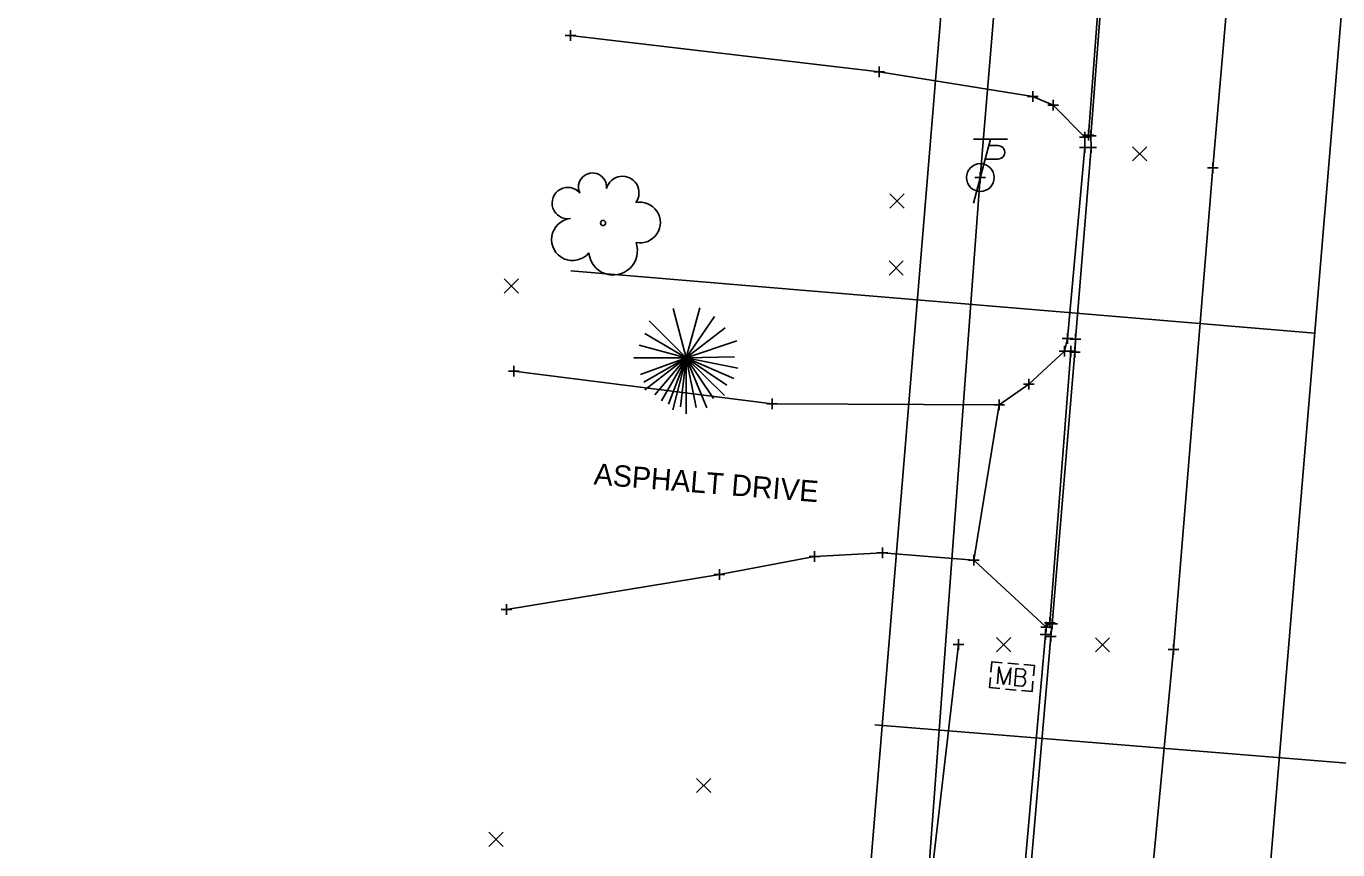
# Model space of a CAD drawing. Extents: x 1380440 to 1381945, y 468756 to 470369.
# Drawn here: x 1381439.7 to 1381562.7, y 469327.1 to 469404.3 of the extents above; entities that cross this region are included whole.
import ezdxf

# ---------------------------------------------------------------- set-up
doc = ezdxf.new("R2010")
doc.units = 0
for name, color, linetype in [('DR_X_Cells', 7, 'Continuous'), ('GE_P_Driveway_CL', 7, 'Continuous'), ('PM_X_CL_Double_Solid', 7, 'Continuous'), ('PV_P_Curb', 7, 'Continuous'), ('PV_X_COP', 7, 'Continuous'), ('RD_P_Cells', 7, 'Continuous'), ('RW_P_Esmt_TMP', 7, 'Continuous'), ('RW_X_Esmt_SH', 7, 'Continuous'), ('SC_Scratch10', 7, 'Continuous'), ('SC_Shading1', 7, 'Continuous'), ('SH_Named_Boundary', 7, 'Continuous'), ('UT_X_Gas', 7, 'Continuous'), ('UT_X_Overhead_Combined', 7, 'Continuous'), ('UT_X_Sanitary_Line', 7, 'Continuous'), ('UT_X_Water', 7, 'Continuous'), ('X-SUBDIVISION', 7, 'Continuous')]:
    doc.layers.add(name, color=color, linetype=linetype)

msp = doc.modelspace()

# ---------------------------------------------------------------- linework, layer by layer
at = {"layer": 'DR_X_Cells'}
for points in [[(1381538.96, 469393.9), (1381538.97, 469392.95), (1381537.34, 469375.04), (1381537.07, 469373.85)], [(1381535.34, 469347.99), (1381535.28, 469347.29), (1381533.36, 469325.49), (1381531.78, 469307.95), (1381530.98, 469305.57), (1381527.65, 469300.02), (1381527.35, 469296.02), (1381529.77, 469292.16), (1381529.97, 469291.26), (1381530.24, 469290.52)]]:
    msp.add_lwpolyline(points, dxfattribs=at)
at = {"layer": 'GE_P_Driveway_CL'}
for p, q in [((1381543.45, 469391.67), (1381544.78, 469393.01)), ((1381543.45, 469393.01), (1381544.78, 469391.67)), ((1381520.69, 469387.24), (1381522.03, 469388.58)), ((1381520.69, 469388.58), (1381522.03, 469387.24)), ((1381520.62, 469380.98), (1381521.95, 469382.32)), ((1381520.62, 469382.32), (1381521.95, 469380.98)), ((1381484.53, 469379.29), (1381485.86, 469380.63)), ((1381484.53, 469380.63), (1381485.86, 469379.29)), ((1381530.69, 469345.66), (1381532.03, 469347)), ((1381530.69, 469347), (1381532.03, 469345.66)), ((1381539.96, 469345.66), (1381541.3, 469346.99)), ((1381539.96, 469346.99), (1381541.3, 469345.66)), ((1381502.57, 469332.47), (1381503.9, 469333.8)), ((1381502.57, 469333.8), (1381503.9, 469332.47)), ((1381483.09, 469327.43), (1381484.43, 469328.77)), ((1381483.09, 469328.77), (1381484.43, 469327.43))]:
    msp.add_line(p, q, dxfattribs=at)
at = {"layer": 'PM_X_CL_Double_Solid'}
msp.add_lwpolyline([(1381555.39, 469442.03), (1381550.97, 469391.02), (1381547.28, 469345.9), (1381541.95, 469289.55), (1381537.19, 469231.27), (1381533.05, 469168.09), (1381530.32, 469133.74), (1381523.97, 469065.08), (1381520.12, 469021.37), (1381518.18, 469001.31)], dxfattribs=at)
at = {"layer": 'PV_P_Curb'}
msp.add_lwpolyline([(1381527.14, 469346.36), (1381524.79, 469326.2), (1381523.85, 469304.1), (1381523.31, 469298.29)], dxfattribs=at)
at = {"layer": 'PV_X_COP'}
for p, q in [((1381530.13, 469393.72), (1381528.52, 469387.72)), ((1381531.73, 469393.72), (1381528.53, 469393.72)), ((1381529.97, 469393.12), (1381530.82, 469393.12)), ((1381529.63, 469391.85), (1381530.82, 469391.85))]:
    msp.add_line(p, q, dxfattribs=at)
msp.add_circle((1381529.17, 469390.12), 1.3, dxfattribs=at)
msp.add_arc((1381530.83, 469392.48), 0.638, 268.8767, 91.1233, dxfattribs=at)
at = {"layer": 'RD_P_Cells'}
for p, q in [((1381531.74, 469344.6), (1381532.74, 469344.51)), ((1381532.14, 469343.34), (1381532.14, 469343.34)), ((1381531.52, 469342.17), (1381532.52, 469342.08))]:
    msp.add_line(p, q, dxfattribs=at)
for points in [[(1381530.17, 469343.77), (1381530.26, 469344.74), (1381531.23, 469344.65)], [(1381530.78, 469342.66), (1381530.92, 469344.25), (1381531.36, 469342.61), (1381532.05, 469344.15), (1381531.91, 469342.56)], [(1381533.17, 469343.32), (1381533.23, 469343.37), (1381533.28, 469343.41), (1381533.3, 469343.44), (1381533.32, 469343.47), (1381533.35, 469343.51), (1381533.36, 469343.55), (1381533.4, 469343.64), (1381533.4, 469343.67), (1381533.41, 469343.72), (1381533.4, 469343.8), (1381533.38, 469343.87), (1381533.35, 469343.92), (1381533.29, 469343.98), (1381533.24, 469344), (1381533.22, 469344.02), (1381533.16, 469344.05), (1381532.54, 469344.11), (1381532.4, 469342.51), (1381533.09, 469342.45), (1381533.18, 469342.49), (1381533.26, 469342.55), (1381533.33, 469342.64), (1381533.38, 469342.75), (1381533.4, 469342.86), (1381533.41, 469342.94), (1381533.39, 469343.02), (1381533.35, 469343.13), (1381533.3, 469343.22), (1381533.17, 469343.32), (1381532.48, 469343.38)], [(1381533.26, 469344.47), (1381534.24, 469344.37), (1381534.16, 469343.41)], [(1381531.01, 469342.22), (1381530.04, 469342.31), (1381530.13, 469343.27)], [(1381534.11, 469342.91), (1381534.02, 469341.94), (1381533.03, 469342.03)]]:
    msp.add_lwpolyline(points, dxfattribs=at)
at = {"layer": 'RW_P_Esmt_TMP'}
msp.add_line((1381533.72, 469370.74), (1381533.72, 469370.74), dxfattribs=at)
msp.add_lwpolyline([(1381541, 469413.22), (1381539.53, 469394.02), (1381539.58, 469392.93), (1381538.09, 469374.98), (1381538.03, 469373.76), (1381535.92, 469348.28), (1381535.79, 469347.09), (1381533.91, 469325.42), (1381532.32, 469307.8), (1381531.56, 469305.55), (1381528.19, 469299.9), (1381527.99, 469296.13), (1381530.34, 469292.53), (1381530.8, 469290.75), (1381530.92, 469290), (1381529.4, 469268.09), (1381529.3, 469267.44), (1381526.47, 469232.31)], dxfattribs=at)
at = {"layer": 'RW_X_Esmt_SH'}
for points in [[(1381540.26, 469413.42), (1381540.77, 469413.29), (1381539.31, 469394.1), (1381538.96, 469393.9)], [(1381490.75, 469403.42), (1381519.7, 469400.04), (1381534.11, 469397.71), (1381535.99, 469396.91), (1381538.96, 469393.9)], [(1381537.07, 469373.85), (1381533.72, 469370.74), (1381530.94, 469368.81), (1381528.58, 469354.27), (1381535.34, 469347.99)], [(1381537.07, 469373.85), (1381537.66, 469373.84), (1381535.7, 469348.38), (1381535.34, 469347.99)], [(1381530.94, 469368.81), (1381509.64, 469368.9), (1381485.43, 469371.98)], [(1381484.73, 469349.64), (1381504.73, 469352.92), (1381513.61, 469354.59), (1381519.99, 469354.96), (1381528.58, 469354.27)]]:
    msp.add_lwpolyline(points, dxfattribs=at)
at = {"layer": 'SC_Scratch10'}
for p, q in [((1381501.6, 469373.21), (1381500.37, 469377.83)), ((1381501.6, 469373.21), (1381502.86, 469377.91)), ((1381501.6, 469373.21), (1381498.11, 469376.7)), ((1381501.6, 469373.21), (1381504.26, 469377.1)), ((1381501.6, 469373.21), (1381505.26, 469376.02)), ((1381501.6, 469373.21), (1381497.7, 469375.51)), ((1381501.6, 469373.21), (1381506.34, 469374.82)), ((1381501.6, 469373.21), (1381497.19, 469374.4)), ((1381496.67, 469373.21), (1381501.6, 469373.21)), ((1381501.6, 469373.21), (1381497.31, 469371.65)), ((1381501.6, 469373.21), (1381497.62, 469370.93)), ((1381501.6, 469373.21), (1381497.7, 469370.22)), ((1381501.6, 469373.21), (1381498.66, 469369.75)), ((1381501.6, 469373.21), (1381499.28, 469369.2)), ((1381501.6, 469373.21), (1381499.94, 469368.87)), ((1381501.6, 469373.21), (1381500.34, 469368.36)), ((1381501.6, 469373.21), (1381501.06, 469368.62)), ((1381501.6, 469373.21), (1381506.11, 469373.3)), ((1381501.6, 469367.97), (1381501.6, 469373.21)), ((1381501.6, 469373.21), (1381502.52, 469368.58)), ((1381501.6, 469373.21), (1381503.54, 469368.54)), ((1381501.6, 469373.21), (1381504.14, 469369.42)), ((1381501.6, 469373.21), (1381505.19, 469369.69)), ((1381501.6, 469373.21), (1381505.42, 469370.66)), ((1381501.6, 469373.21), (1381506.07, 469371.27)), ((1381501.6, 469373.21), (1381506.43, 469372.25))]:
    msp.add_line(p, q, dxfattribs=at)
msp.add_circle((1381493.8, 469385.86), 0.24, dxfattribs=at)
for centre, radius, start, end in [((1381492.81, 469389.23), 1.32, 354.0047, 205.9741), ((1381495.62, 469388.69), 1.55, 323.83, 165.0376), ((1381490.49, 469387.73), 1.47, 39.0625, 279.5412), ((1381497.26, 469385.9), 1.91, 259.1453, 101.4596), ((1381490.94, 469384.31), 1.97, 96.1722, 320.5737), ((1381494.74, 469383.26), 2.28, 184.9476, 19.4572)]:
    msp.add_arc(centre, radius, start, end, dxfattribs=at)
at = {"layer": 'SC_Shading1'}
msp.add_lwpolyline([(1381555.39, 469442.03), (1381550.97, 469391.02), (1381547.28, 469345.9), (1381541.95, 469289.55), (1381537.19, 469231.27), (1381533.05, 469168.09), (1381530.32, 469133.74), (1381523.97, 469065.08), (1381520.12, 469021.37), (1381518.18, 469001.31)], dxfattribs=at)
at = {"layer": 'SH_Named_Boundary'}
for p, q in [((1381490.25, 469403.42), (1381491.25, 469403.42)), ((1381490.75, 469403.92), (1381490.75, 469402.92)), ((1381490.75, 469403.42), (1381490.75, 469403.42)), ((1381519.7, 469400.54), (1381519.7, 469399.54)), ((1381519.2, 469400.04), (1381520.2, 469400.04)), ((1381519.7, 469400.04), (1381519.7, 469400.04)), ((1381534.11, 469398.21), (1381534.11, 469397.21)), ((1381533.61, 469397.71), (1381534.61, 469397.71)), ((1381534.11, 469397.71), (1381534.11, 469397.71)), ((1381535.49, 469396.91), (1381536.49, 469396.91)), ((1381535.99, 469397.41), (1381535.99, 469396.41)), ((1381535.99, 469396.91), (1381535.99, 469396.91)), ((1381538.96, 469394.4), (1381538.96, 469393.4)), ((1381538.96, 469394.4), (1381538.96, 469393.4)), ((1381538.96, 469394.4), (1381538.96, 469393.4)), ((1381539.31, 469394.6), (1381539.31, 469393.6)), ((1381539.53, 469394.52), (1381539.53, 469393.52)), ((1381538.46, 469393.9), (1381539.46, 469393.9)), ((1381538.46, 469393.9), (1381539.46, 469393.9)), ((1381538.46, 469393.9), (1381539.46, 469393.9)), ((1381538.81, 469394.1), (1381539.81, 469394.1)), ((1381538.96, 469393.9), (1381538.96, 469393.9)), ((1381538.96, 469393.9), (1381538.96, 469393.9)), ((1381538.96, 469393.9), (1381538.96, 469393.9)), ((1381538.97, 469393.45), (1381538.97, 469392.45)), ((1381539.03, 469394.02), (1381540.03, 469394.02)), ((1381539.31, 469394.1), (1381539.31, 469394.1)), ((1381539.53, 469394.02), (1381539.53, 469394.02)), ((1381539.58, 469393.43), (1381539.58, 469392.43)), ((1381538.47, 469392.95), (1381539.47, 469392.95)), ((1381538.97, 469392.95), (1381538.97, 469392.95)), ((1381539.08, 469392.93), (1381540.08, 469392.93)), ((1381539.58, 469392.93), (1381539.58, 469392.93)), ((1381550.47, 469391.02), (1381551.47, 469391.02)), ((1381550.97, 469391.52), (1381550.97, 469390.52)), ((1381550.97, 469391.02), (1381550.97, 469391.02)), ((1381528.67, 469390.12), (1381529.67, 469390.12)), ((1381528.67, 469390.12), (1381529.67, 469390.12)), ((1381529.17, 469390.62), (1381529.17, 469389.62)), ((1381529.17, 469390.62), (1381529.17, 469389.62)), ((1381529.17, 469390.12), (1381529.17, 469390.12)), ((1381529.17, 469390.12), (1381529.17, 469390.12)), ((1381536.84, 469375.04), (1381537.84, 469375.04)), ((1381537.34, 469375.54), (1381537.34, 469374.54)), ((1381537.34, 469375.04), (1381537.34, 469375.04)), ((1381537.59, 469374.98), (1381538.59, 469374.98)), ((1381538.09, 469375.48), (1381538.09, 469374.48)), ((1381538.09, 469374.98), (1381538.09, 469374.98)), ((1381536.57, 469373.85), (1381537.57, 469373.85)), ((1381536.57, 469373.85), (1381537.57, 469373.85)), ((1381536.57, 469373.85), (1381537.57, 469373.85)), ((1381537.07, 469374.35), (1381537.07, 469373.35)), ((1381537.07, 469374.35), (1381537.07, 469373.35)), ((1381537.07, 469374.35), (1381537.07, 469373.35)), ((1381537.07, 469373.85), (1381537.07, 469373.85)), ((1381537.07, 469373.85), (1381537.07, 469373.85)), ((1381537.07, 469373.85), (1381537.07, 469373.85)), ((1381537.16, 469373.84), (1381538.16, 469373.84)), ((1381537.53, 469373.76), (1381538.53, 469373.76)), ((1381537.66, 469374.34), (1381537.66, 469373.34)), ((1381537.66, 469373.84), (1381537.66, 469373.84)), ((1381538.03, 469374.26), (1381538.03, 469373.26)), ((1381538.03, 469373.76), (1381538.03, 469373.76)), ((1381485.43, 469372.48), (1381485.43, 469371.48)), ((1381484.93, 469371.98), (1381485.93, 469371.98)), ((1381485.43, 469371.98), (1381485.43, 469371.98)), ((1381533.72, 469371.24), (1381533.72, 469370.24)), ((1381533.72, 469371.24), (1381533.72, 469370.24)), ((1381533.22, 469370.74), (1381534.22, 469370.74)), ((1381533.22, 469370.74), (1381534.22, 469370.74)), ((1381533.72, 469370.74), (1381533.72, 469370.74)), ((1381533.72, 469370.74), (1381533.72, 469370.74)), ((1381509.14, 469368.9), (1381510.14, 469368.9)), ((1381509.64, 469369.4), (1381509.64, 469368.4)), ((1381509.64, 469368.9), (1381509.64, 469368.9)), ((1381530.44, 469368.81), (1381531.44, 469368.81)), ((1381530.44, 469368.81), (1381531.44, 469368.81)), ((1381530.94, 469369.31), (1381530.94, 469368.31)), ((1381530.94, 469369.31), (1381530.94, 469368.31)), ((1381530.94, 469368.81), (1381530.94, 469368.81)), ((1381530.94, 469368.81), (1381530.94, 469368.81)), ((1381513.61, 469355.09), (1381513.61, 469354.09)), ((1381519.99, 469355.46), (1381519.99, 469354.46)), ((1381513.11, 469354.59), (1381514.11, 469354.59)), ((1381513.61, 469354.59), (1381513.61, 469354.59)), ((1381519.49, 469354.96), (1381520.49, 469354.96)), ((1381519.99, 469354.96), (1381519.99, 469354.96)), ((1381528.08, 469354.27), (1381529.08, 469354.27)), ((1381528.08, 469354.27), (1381529.08, 469354.27)), ((1381528.58, 469354.77), (1381528.58, 469353.77)), ((1381528.58, 469354.77), (1381528.58, 469353.77)), ((1381528.58, 469354.27), (1381528.58, 469354.27)), ((1381528.58, 469354.27), (1381528.58, 469354.27)), ((1381504.23, 469352.92), (1381505.23, 469352.92)), ((1381504.73, 469353.42), (1381504.73, 469352.42)), ((1381504.73, 469352.92), (1381504.73, 469352.92)), ((1381484.73, 469350.14), (1381484.73, 469349.14)), ((1381484.23, 469349.64), (1381485.23, 469349.64)), ((1381484.73, 469349.64), (1381484.73, 469349.64)), ((1381535.7, 469348.88), (1381535.7, 469347.88)), ((1381534.84, 469347.99), (1381535.84, 469347.99)), ((1381534.84, 469347.99), (1381535.84, 469347.99)), ((1381534.84, 469347.99), (1381535.84, 469347.99)), ((1381535.2, 469348.38), (1381536.2, 469348.38)), ((1381535.28, 469347.79), (1381535.28, 469346.79)), ((1381535.34, 469348.49), (1381535.34, 469347.49)), ((1381535.34, 469348.49), (1381535.34, 469347.49)), ((1381535.34, 469348.49), (1381535.34, 469347.49)), ((1381535.34, 469347.99), (1381535.34, 469347.99)), ((1381535.34, 469347.99), (1381535.34, 469347.99)), ((1381535.34, 469347.99), (1381535.34, 469347.99)), ((1381535.42, 469348.28), (1381536.42, 469348.28)), ((1381535.7, 469348.38), (1381535.7, 469348.38)), ((1381535.92, 469348.78), (1381535.92, 469347.78)), ((1381535.92, 469348.28), (1381535.92, 469348.28)), ((1381527.14, 469346.86), (1381527.14, 469345.86)), ((1381534.78, 469347.29), (1381535.78, 469347.29)), ((1381535.28, 469347.29), (1381535.28, 469347.29)), ((1381535.29, 469347.09), (1381536.29, 469347.09)), ((1381535.79, 469347.59), (1381535.79, 469346.59)), ((1381535.79, 469347.09), (1381535.79, 469347.09)), ((1381547.28, 469346.4), (1381547.28, 469345.4)), ((1381526.64, 469346.36), (1381527.64, 469346.36)), ((1381527.14, 469346.36), (1381527.14, 469346.36)), ((1381546.78, 469345.9), (1381547.78, 469345.9)), ((1381547.28, 469345.9), (1381547.28, 469345.9))]:
    msp.add_line(p, q, dxfattribs=at)
at = {"layer": 'UT_X_Gas'}
msp.add_lwpolyline([(1381485.9, 468926.41), (1381594.27, 470237.89), (1380558, 470279.29)], dxfattribs=at)
at = {"layer": 'UT_X_Overhead_Combined'}
msp.add_lwpolyline([(1381540.8, 469054.26), (1381515.28, 469203.1), (1381529.17, 469390.12), (1381543.86, 469565.78), (1381559.77, 469757.41), (1381571.97, 469887.64), (1381581.26, 470018.2), (1381595.79, 470220.83), (1381665.56, 470247.4)], dxfattribs=at)
at = {"layer": 'UT_X_Sanitary_Line'}
msp.add_line((1381568.26, 469334.85), (1381519.27, 469338.83), dxfattribs=at)
at = {"layer": 'UT_X_Water'}
for p, q in [((1381545.41, 469194.71), (1381630.26, 470209.69)), ((1381560.53, 469375.52), (1381490.78, 469381.39))]:
    msp.add_line(p, q, dxfattribs=at)

# ---------------------------------------------------------------- texts
at = {"layer": 'X-SUBDIVISION'}
msp.add_text('ASPHALT DRIVE', height=2, rotation=355.4428, dxfattribs=at).set_placement((1381492.88, 469361.36))

doc.saveas('drawing.dxf')
